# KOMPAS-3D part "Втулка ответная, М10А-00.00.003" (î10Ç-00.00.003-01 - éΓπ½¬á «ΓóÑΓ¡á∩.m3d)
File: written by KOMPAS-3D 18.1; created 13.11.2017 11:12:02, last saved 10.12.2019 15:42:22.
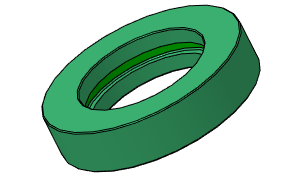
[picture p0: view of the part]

Document properties: Автор: Мирончук; Организация: Мирончук; Полное имя файла: D:\Magna\Магна Ins\Магна ins 10\М10-00.00.000\3Д\М10А-00.00.003-01 - Втулка ответная.m3d

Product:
- Part/product: Втулка ответная  | designation М10А-00.00.003
    Масса: 0.0181346
  - Component: Втулка ответная  | designation М10А-00.00.003-01  | Масса: 0.0274435; Раздел спецификации: Детали; Форматы листов документа: А4; source file: М10А-00.00.003 - Втулка ответная.m3d
- Part/product: Втулка ответная  | designation М10А-00.00.003-01
    Масса: 0.0316343
    Раздел спецификации: Детали
    Форматы листов документа: А4
    source file: М10А-00.00.003 - Втулка ответная.m3d

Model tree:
1. Эскиз:1
2. Операция вращения:1
     Угол 1 = 360
3. Скругление:2
     Радиус = 0.4
4. Фаска:1
     Угол = 45; Длина 1 = 0.3; Длина 2 = 0.3

Expressions: 34.1/2; 46.9/2; 54/2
